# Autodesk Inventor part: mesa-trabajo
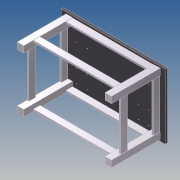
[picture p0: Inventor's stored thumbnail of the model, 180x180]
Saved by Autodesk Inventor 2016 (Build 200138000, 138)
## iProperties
Created: 2012-05
Part Number: mesa-trabajo
Material: Generic
Document SubType Name: Modeling
Designer: julian.chica
Density: 1 g/cm^3
Appearance: Default
Mass: 111241 g
Surface Area: 63758.8 cm^2
Volume: 111241 cm^3
Author: julian.chica
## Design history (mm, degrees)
sketch "Sketch2"
  geometry: L1 (-800, 500)-(800, 500); L2 (800, 500)-(800, -500); L3 (800, -500)-(-800, -500); L4 (-800, -500)-(-800, 500); 3 further points
  constraints: 8 end point, 2 midpoint, 2 parallel, 1 horizontal, 1 horizontal alignment, 1 perpendicular, 1 vertical alignment
  dimensions: "d0" = 1600 distance of L2.end L3.end; "d1" = 1000 distance of L1.end L2.end
extrude "Extrusion1" new body sketch "Sketch2" distance "d2" = 38.1; taper "d3" = 0 deg
sketch "Sketch3"
  geometry: L1 (800, 500)-(800, -500) reference; L2 (-800, 500)-(800, 500) reference; L3 (-800, -500)-(-800, 500) reference; L4 (800, -500)-(-800, -500) reference; L5 (720, 470)-(720, -470); L6 (720, -470)-(-720, -470); L7 (-720, -470)-(-720, 470); L8 (-720, 470)-(720, 470); L9 (694.6, 444.6)-(694.6, -444.6); L10 (694.6, -444.6)-(-694.6, -444.6); L11 (-694.6, -444.6)-(-694.6, 444.6); L12 (-694.6, 444.6)-(694.6, 444.6); 1 further point
  constraints: 16 end point, 3 other
  dimensions: "d4" = 25.4 distance between parallel lines of L12 L8; "d8" = 30 distance between parallel lines of L2 L8; "d9" = 30 distance between parallel lines of L4 L6; "d10" = 80 distance between parallel lines of L1 L5; "d11" = 80 distance between parallel lines of L3 L7
extrude "Extrusion2" join sketch "Sketch3" distance "d6" = 100; taper "d7" = 0 deg
sketch "Sketch4"
  geometry: L1 (-720, 470)-(-630, 470); L2 (-630, 470)-(-630, 380); L3 (-630, 380)-(-720, 380); L4 (-720, 380)-(-720, 470); L5 (-725, 375)-(-625, 375); L6 (-625, 375)-(-625, 475); L7 (-625, 475)-(-725, 475); L8 (-725, 475)-(-725, 375); L9 (625, 375)-(725, 375); L10 (725, 375)-(725, 475); L11 (725, 475)-(625, 475); L12 (625, 475)-(625, 375); L13 (-725, -475)-(-625, -475); L14 (-625, -475)-(-625, -375); L15 (-625, -375)-(-725, -375); L16 (-725, -375)-(-725, -475); L17 (625, -475)-(725, -475); L18 (725, -475)-(725, -375); L19 (725, -375)-(625, -375); L20 (625, -375)-(625, -475); 3 further points
  constraints: 40 end point, 4 parallel, 2 horizontal, 2 perpendicular, 1 vertical, 27 other
  dimensions: "d12" = 90 distance of L2.end L3.end; "d13" = 90 distance of L1.end L2.end; "d14" = 5 distance between parallel lines of L3 L5; "d17" = 1350 distance of L5.start L9.start; "d20" = 850 distance of L5.start L13.start
extrude "Extrusion3" join sketch "Sketch4" distance "d23" = 750; taper "d24" = 0 deg
pattern_linear "Rectangular Pattern1" dims "d27" = 500
sketch "Sketch5"
  geometry: L1 (800, -500)-(-800, -500) reference; L2 (800, 500)-(800, -500) reference; 5 further points
  constraints: 2 horizontal alignment, 2 vertical alignment
  dimensions: "d28" = 160 distance of point (550, -380) point (390, -380); "d29" = 205 distance of point (390, -380) point (390, -175); "d30" = 120 distance from line of L1 point (550, -380); "d31" = 250 distance from line of L2 point (550, -380)
hole "Hole1" sketch "Sketch5" at (390, -175), (550, -175), (550, -380), (390, -380) diameter "d32" = 9; stored, may be unused: countersink angle "d36" = 90 deg, drill point angle "d38" = 118 deg; dims "d33" = 6, "d34" = 4, "d35" = 2, "d37" = 8
pattern_linear "Rectangular Pattern2" dims "d41" = 950
body "Solid1"
